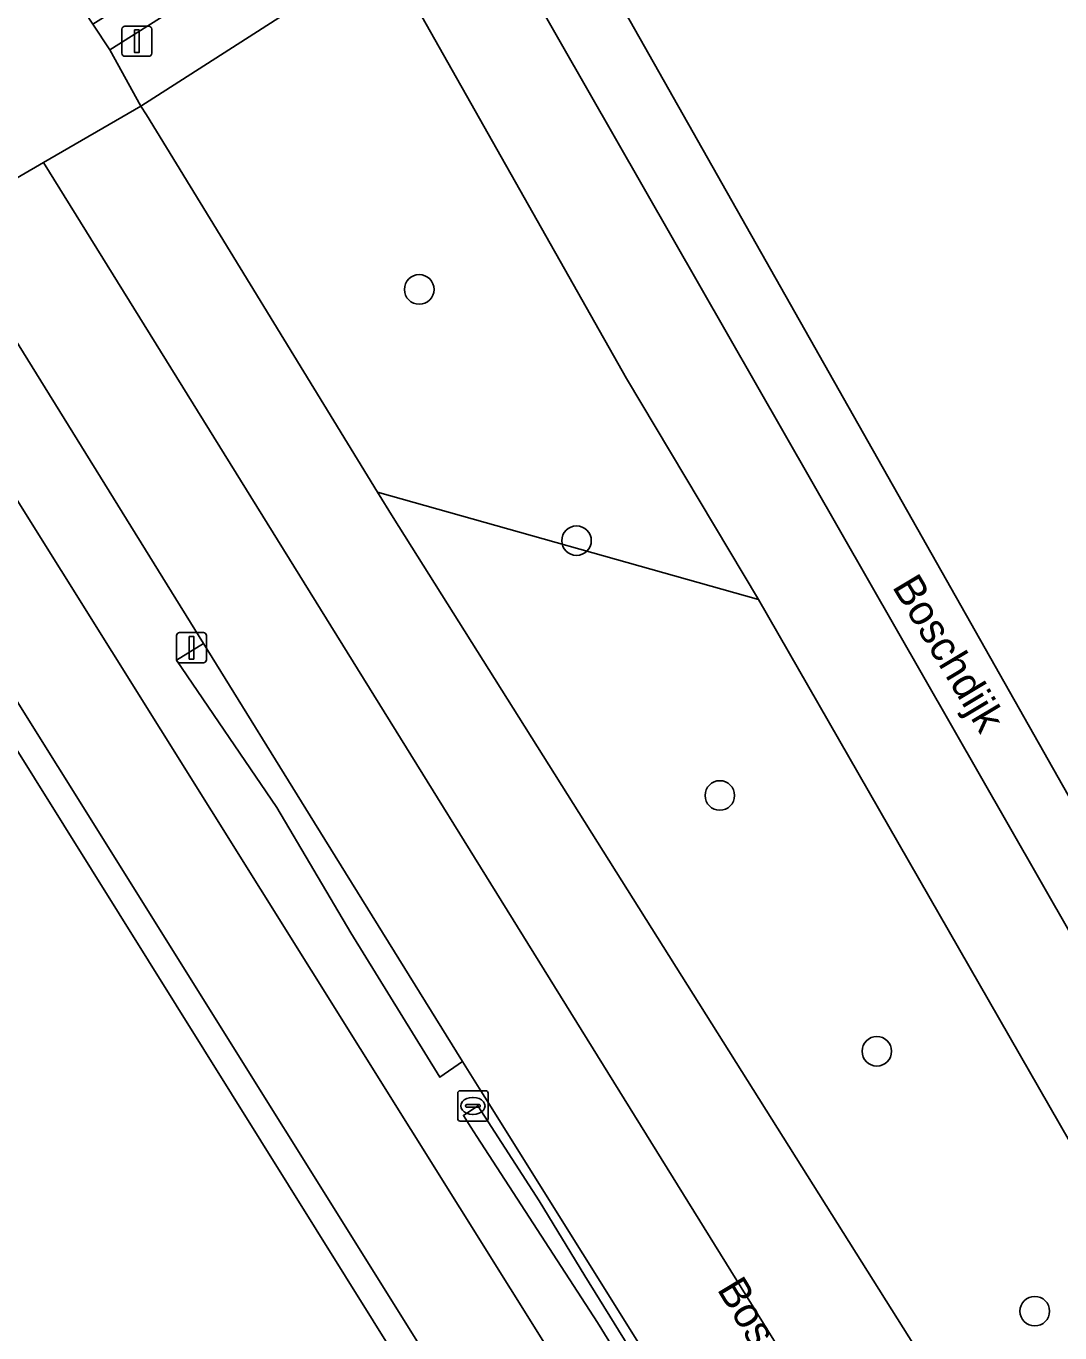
# Model space of a CAD drawing. Extents: x 156702 to 158052, y 387630 to 388992.
# Drawn here: x 157988.09 to 158022.32, y 388524.28 to 388567.55 of the extents above; entities that cross this region are included whole.
import ezdxf

# ---------------------------------------------------------------- set-up
doc = ezdxf.new("R2010")
doc.units = 0
for name, color, linetype in [('IMGEO_Berm_groen', 7, 'Continuous'), ('IMGEO_Berm_open', 7, 'Continuous'), ('IMGEO_Boom', 7, 'Continuous'), ('IMGEO_Erf', 7, 'Continuous'), ('IMGEO_Fietspad_gesloten', 7, 'Continuous'), ('IMGEO_Groenvoorziening', 7, 'Continuous'), ('IMGEO_Haag', 7, 'Continuous'), ('IMGEO_Kolk', 7, 'Continuous'), ('IMGEO_Lichtmast', 7, 'Continuous'), ('IMGEO_Openbare_ruimte_label', 7, 'Continuous'), ('IMGEO_Rijbaan_regionaal_gesloten', 7, 'Continuous'), ('IMGEO_Verkeerseiland_open', 7, 'Continuous'), ('IMGEO_Verkeersregelinstallatiepaal', 7, 'Continuous'), ('IMGEO_Voetpad_open', 7, 'Continuous')]:
    doc.layers.add(name, color=color, linetype=linetype)

msp = doc.modelspace()

# ---------------------------------------------------------------- linework, layer by layer
at = {"layer": 'IMGEO_Berm_groen'}
msp.add_lwpolyline([(158000.144, 388569.732), (157999.928, 388570.045), (157991.896, 388564.897), (157992.08, 388564.61), (157999.726, 388552.122), (158012.344, 388548.558), (158007.97, 388555.875)], close=True, dxfattribs=at)
for points in [[(158028.096, 388492.411), (158023.349, 388500), (158022.089, 388502.015), (158003.41, 388531.875), (158003.15, 388532.293), (158002.545, 388533.269), (158001.792, 388532.747), (157998.843, 388537.53), (157996.392, 388541.677), (157993.077, 388546.553), (157993.966, 388547.104), (157985.306, 388561.079), (157985.05, 388560.92), (157985.075, 388560.876), (157985.1, 388560.833), (157984.557, 388560.507), (157983.17, 388559.673)], [(157983.092, 388558.989), (157984.323, 388557.397), (158018.945, 388502.054), (158022.14, 388496.912)], [(158044.617, 388492.351), (158040.225, 388500), (158034.603, 388509.791), (158012.344, 388548.558), (157999.726, 388552.122), (158000.243, 388551.278), (158028.672, 388506.106), (158032.483, 388500), (158036.104, 388494.199), (158043.12, 388482.757)], [(158034.866, 388474.89), (158035.74, 388475.722), (158035.156, 388476.858), (158032.752, 388481.256), (158030.403, 388485.599), (158027.645, 388490.734), (158025.842, 388494.011), (158024.476, 388496.251), (158016.473, 388509.307), (158007.009, 388524.631), (158003.017, 388530.78), (158002.816, 388531.09), (158002.57, 388531.486), (158003.048, 388531.8), (158005.083, 388528.659), (158006.585, 388526.174), (158014.793, 388512.94), (158022.878, 388499.857), (158026.252, 388494.23), (158029.01, 388489.45), (158032.097, 388483.823), (158035.62, 388477.022), (158036.121, 388476.086), (158036.432, 388476.382)]]:
    msp.add_lwpolyline(points, dxfattribs=at)
at = {"layer": 'IMGEO_Berm_open'}
msp.add_lwpolyline([(157997.644, 388541.173), (157993.966, 388547.104), (157993.077, 388546.553), (157996.392, 388541.677), (157998.843, 388537.53), (158001.792, 388532.747), (158002.545, 388533.269)], close=True, dxfattribs=at)
at = {"layer": 'IMGEO_Boom'}
for centre in [(158001.108, 388558.829), (158006.316, 388550.511), (158011.059, 388542.076), (158016.257, 388533.607), (158021.486, 388525.003)]:
    msp.add_circle(centre, 0.489, dxfattribs=at)
at = {"layer": 'IMGEO_Erf'}
msp.add_lwpolyline([(157919.17, 388537.784), (157901.376, 388526.898), (157892.719, 388521.727), (157888.385, 388519.102), (157908.338, 388496.924), (157944.942, 388455.967), (158015.435, 388499.288), (157980.926, 388554.569)], dxfattribs=at)
at = {"layer": 'IMGEO_Fietspad_gesloten'}
msp.add_lwpolyline([(158022.14, 388496.912), (158018.945, 388502.054), (157984.323, 388557.397), (157981.106, 388555.846), (157981.664, 388554.989), (158019.082, 388495.141)], dxfattribs=at)
at = {"layer": 'IMGEO_Groenvoorziening'}
msp.add_lwpolyline([(158036.121, 388476.086), (158035.62, 388477.022), (158032.097, 388483.823), (158029.01, 388489.45), (158026.252, 388494.23), (158022.878, 388499.857), (158014.793, 388512.94), (158006.585, 388526.174), (158005.083, 388528.659), (158003.048, 388531.8), (158002.57, 388531.486), (158002.816, 388531.09), (158003.017, 388530.78), (158007.009, 388524.631), (158016.473, 388509.307), (158024.476, 388496.251), (158025.842, 388494.011), (158027.645, 388490.734), (158030.403, 388485.599), (158032.752, 388481.256), (158035.156, 388476.858), (158035.74, 388475.722)], close=True, dxfattribs=at)
at = {"layer": 'IMGEO_Haag'}
msp.add_lwpolyline([(158036.121, 388476.086), (158035.62, 388477.022), (158032.097, 388483.823), (158029.01, 388489.45), (158026.252, 388494.23), (158022.878, 388499.857), (158014.793, 388512.94), (158006.585, 388526.174), (158005.083, 388528.659), (158003.048, 388531.8), (158002.57, 388531.486), (158002.816, 388531.09), (158003.017, 388530.78), (158007.009, 388524.631), (158016.473, 388509.307), (158024.476, 388496.251), (158025.842, 388494.011), (158027.645, 388490.734), (158030.403, 388485.599), (158032.752, 388481.256), (158035.156, 388476.858), (158035.74, 388475.722)], close=True, dxfattribs=at)
at = {"layer": 'IMGEO_Kolk'}
for p, q in [((158002.459, 388532.298), (158003.311, 388532.298)), ((158002.384, 388531.372), (158002.384, 388532.224)), ((158002.686, 388531.841), (158003.084, 388531.841)), ((158002.872, 388532.078), (158002.897, 388532.078)), ((158003.385, 388532.224), (158003.385, 388531.372)), ((158002.643, 388531.792), (158002.643, 388531.804)), ((158003.081, 388531.755), (158002.683, 388531.755)), ((158002.895, 388531.518), (158002.87, 388531.518)), ((158003.127, 388531.804), (158003.127, 388531.792)), ((158003.311, 388531.298), (158002.459, 388531.298))]:
    msp.add_line(p, q, dxfattribs=at)
for points in [[(158002.459, 388532.298), (158003.311, 388532.298)], [(158002.384, 388531.372), (158002.384, 388532.224)], [(158003.385, 388532.224), (158003.385, 388531.372)], [(158003.311, 388531.298), (158002.459, 388531.298)]]:
    msp.add_lwpolyline(points, dxfattribs=at)
for centre, radius, start, end in [((158002.461, 388532.222), 0.0765, 91.552, 178.448), ((158002.461, 388532.222), 0.0765, 91.552, 178.448), ((158003.309, 388532.222), 0.0765, 1.552, 88.448), ((158003.309, 388532.222), 0.0765, 1.552, 88.448), ((158002.683, 388531.801), 0.0403, 85.8775, 175.7526), ((158003.088, 388531.803), 0.0386, 1.7309, 96.639), ((158002.68, 388531.791), 0.0366, 178.938, 274.7102), ((158003.084, 388531.798), 0.043, 264.8664, 352.4533), ((158002.461, 388531.374), 0.0765, 181.552, 268.448), ((158002.461, 388531.374), 0.0765, 181.552, 268.448), ((158003.309, 388531.374), 0.0765, 271.552, 358.448), ((158003.309, 388531.374), 0.0765, 271.552, 358.448)]:
    msp.add_arc(centre, radius, start, end, dxfattribs=at)
for centre, major_axis, ratio, start_param, end_param in [((158002.871, 388531.798), (-0.387, 0.002), 0.722429, 4.712389, 7.853982), ((158002.896, 388531.798), (-0.39, 0.002), 0.717154, 1.570796, 4.712389)]:
    msp.add_ellipse(centre, major_axis=major_axis, ratio=ratio, start_param=start_param, end_param=end_param, dxfattribs=at)
at = {"layer": 'IMGEO_Lichtmast'}
for p, q in [((157993.172, 388547.468), (157993.962, 388547.468)), ((157993.962, 388547.468), (157993.172, 388547.468)), ((157993.072, 388546.568), (157993.072, 388547.368)), ((157993.072, 388547.368), (157993.072, 388546.568)), ((157994.062, 388547.368), (157994.062, 388546.568)), ((157994.062, 388546.568), (157994.062, 388547.368)), ((157993.962, 388546.468), (157993.172, 388546.468)), ((157993.172, 388546.468), (157993.962, 388546.468))]:
    msp.add_line(p, q, dxfattribs=at)
msp.add_lwpolyline([(157993.492, 388547.343), (157993.642, 388547.343), (157993.642, 388546.593), (157993.492, 388546.593), (157993.492, 388547.343)], dxfattribs=at)
for centre, start, end in [((157993.172, 388547.368), 90, 180), ((157993.172, 388547.368), 90, 180), ((157993.962, 388547.368), 0, 90), ((157993.962, 388547.368), 360, 90), ((157993.172, 388546.568), 180, 270), ((157993.172, 388546.568), 180, 270), ((157993.962, 388546.568), 270, 0), ((157993.962, 388546.568), 270, 0)]:
    msp.add_arc(centre, 0.1, start, end, dxfattribs=at)
at = {"layer": 'IMGEO_Rijbaan_regionaal_gesloten'}
for points in [[(157985.05, 388560.92), (157985.306, 388561.079), (157988.674, 388563.03), (157991.896, 388564.897), (157990.87, 388566.763), (157990.303, 388567.608), (157988.653, 388570.123), (157986.443, 388573.863), (157974.135, 388593.488)], [(158050.158, 388489.466), (158037.507, 388511.572), (158020.603, 388541.113), (158002.978, 388571.912), (157999.928, 388570.045), (158000.144, 388569.732), (158007.97, 388555.875), (158012.344, 388548.558), (158034.603, 388509.791), (158040.225, 388500), (158044.617, 388492.351)], [(158037.861, 388477.745), (158040.245, 388480.017), (158025.305, 388504.014), (158015.496, 388519.769), (157988.674, 388563.03), (157985.306, 388561.079), (157993.966, 388547.104), (157997.644, 388541.173), (158002.545, 388533.269), (158003.15, 388532.293), (158003.41, 388531.875), (158022.089, 388502.015), (158023.349, 388500), (158028.096, 388492.411)]]:
    msp.add_lwpolyline(points, dxfattribs=at)
for points in [[(158051.596, 388490.837), (158005.013, 388573.158), (158002.978, 388571.912), (158020.603, 388541.113), (158037.507, 388511.572), (158050.158, 388489.466)], [(158043.12, 388482.757), (158036.104, 388494.199), (158032.483, 388500), (158028.672, 388506.106), (158000.243, 388551.278), (157999.726, 388552.122), (157992.08, 388564.61), (157991.896, 388564.897), (157988.674, 388563.03), (158015.496, 388519.769), (158025.305, 388504.014), (158040.245, 388480.017)]]:
    msp.add_lwpolyline(points, close=True, dxfattribs=at)
at = {"layer": 'IMGEO_Verkeerseiland_open'}
msp.add_lwpolyline([(157990.87, 388566.763), (157998.909, 388571.847), (157998.425, 388572.709), (157990.303, 388567.608)], close=True, dxfattribs=at)
at = {"layer": 'IMGEO_Verkeersregelinstallatiepaal'}
for p, q in [((157991.265, 388566.646), (157991.265, 388567.446)), ((157991.265, 388567.446), (157991.265, 388566.646)), ((157991.365, 388567.546), (157992.155, 388567.546)), ((157992.155, 388567.546), (157991.365, 388567.546)), ((157992.255, 388567.446), (157992.255, 388566.646)), ((157992.255, 388566.646), (157992.255, 388567.446)), ((157992.155, 388566.546), (157991.365, 388566.546)), ((157991.365, 388566.546), (157992.155, 388566.546))]:
    msp.add_line(p, q, dxfattribs=at)
msp.add_lwpolyline([(157991.685, 388567.421), (157991.835, 388567.421), (157991.835, 388566.671), (157991.685, 388566.671), (157991.685, 388567.421)], dxfattribs=at)
for centre, start, end in [((157991.365, 388567.446), 90, 180), ((157991.365, 388567.446), 90, 180), ((157992.155, 388567.446), 0, 90), ((157992.155, 388567.446), 360, 90), ((157991.365, 388566.646), 180, 270), ((157991.365, 388566.646), 180, 270), ((157992.155, 388566.646), 270, 0), ((157992.155, 388566.646), 270, 0)]:
    msp.add_arc(centre, 0.1, start, end, dxfattribs=at)
at = {"layer": 'IMGEO_Voetpad_open'}
msp.add_lwpolyline([(157990.87, 388566.763), (157991.896, 388564.897), (157999.928, 388570.045), (157998.909, 388571.847)], close=True, dxfattribs=at)
msp.add_lwpolyline([(157980.926, 388554.569), (158015.435, 388499.288), (158017.668, 388495.712), (158018.622, 388494.25), (158019.082, 388495.141), (157981.664, 388554.989), (157981.106, 388555.846)], dxfattribs=at)

# ---------------------------------------------------------------- texts
at = {"layer": 'IMGEO_Openbare_ruimte_label'}
for rotation, p in [(300.9245, (158016.748, 388548.989)), (301.1308, (158010.949, 388525.729))]:
    msp.add_text('Boschdijk', height=1, rotation=rotation, dxfattribs=at).set_placement(p)

doc.saveas('drawing.dxf')
